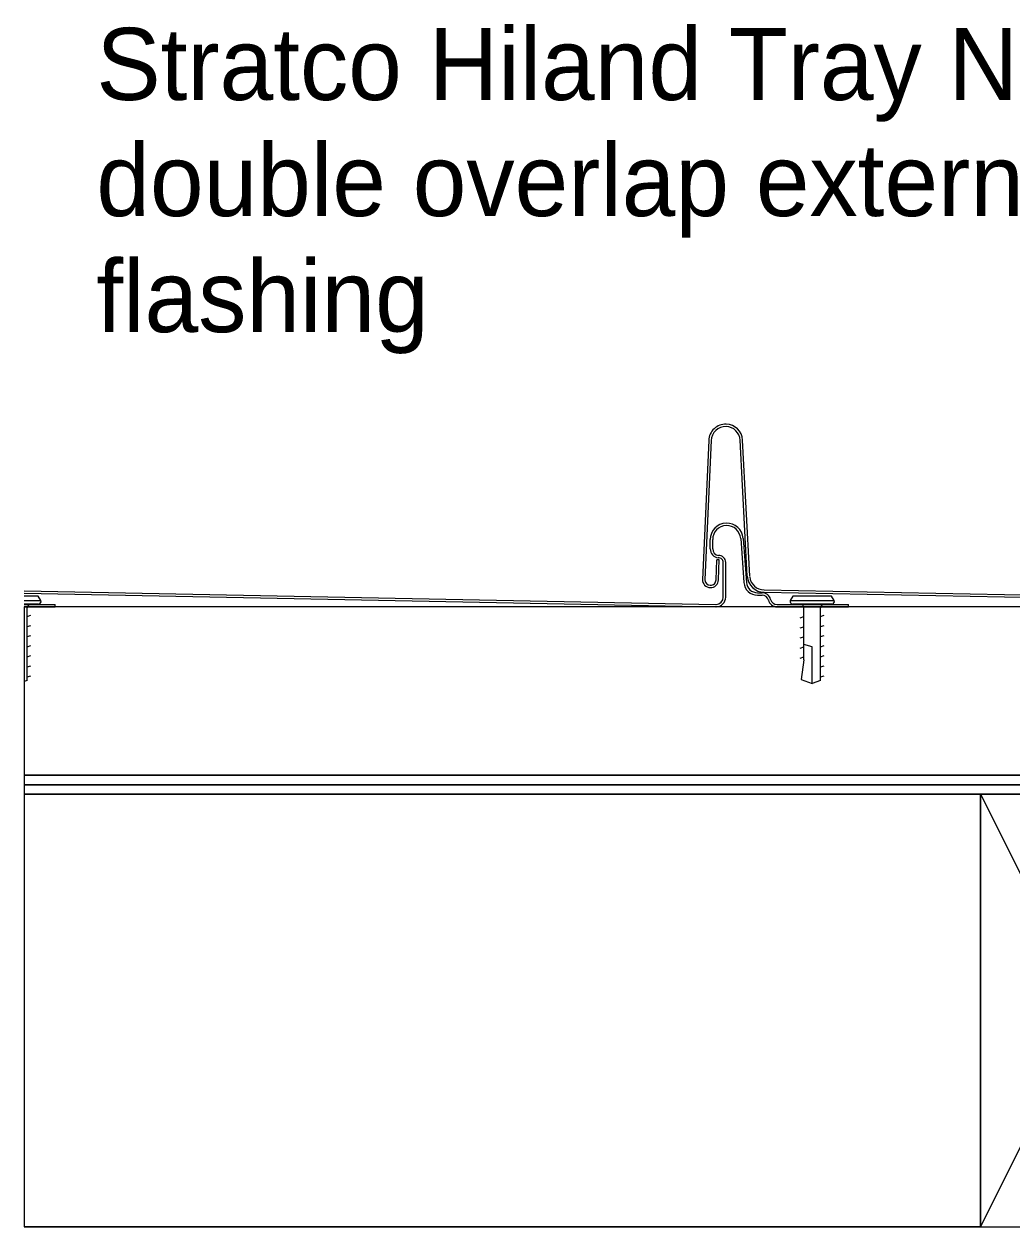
# Model space of a CAD drawing. Extents: x -2.36 to 6.66, y -3.72 to 4.13.
# Drawn here: x 1.2345 to 1.4399, y -3.129 to -2.8788 of the extents above; entities that cross this region are included whole.
import ezdxf

# ---------------------------------------------------------------- set-up
doc = ezdxf.new("R2010")
doc.units = 0
for name, color, linetype in [('A-____-____-IDEN', 7, 'Continuous'), ('A-DETL-____-MEDM', 7, 'Continuous'), ('A-DETL-GENF-OTLN', 7, 'Continuous'), ('A-WALL-____-MCUT', 7, 'Continuous'), ('A-WALL-____-PATT', 7, 'Continuous')]:
    doc.layers.add(name, color=color, linetype=linetype)

# ---------------------------------------------------------------- blocks, each defined once
blk = doc.blocks.new('Detail Repeating_Stratco_Hiland_Tray_Nailstrip - Rib Height 38mm_165mm Coverage-V13-Detail Flashings - Hiland Nailstrip Corner')
at = {"layer": 'A-DETL-____-MEDM'}
for p, q in [((0.32648096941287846, 0.03458502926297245), (0.32517240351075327, 0.005699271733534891)), ((0.32698063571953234, 0.034566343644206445), (0.32567207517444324, 0.005680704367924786)), ((0.3344987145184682, 0.0063452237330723), (0.33301561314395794, 0.0346381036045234)), ((0.3349980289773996, 0.00637139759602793), (0.3335149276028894, 0.03466427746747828)), ((0.3267942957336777, 0.012056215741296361), (0.3267942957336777, 0.013973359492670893)), ((0.3272942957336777, 0.012056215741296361), (0.3272942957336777, 0.013973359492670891)), ((0.33313551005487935, 0.014184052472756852), (0.3337958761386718, 0.005042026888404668)), ((0.3336342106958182, 0.014220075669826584), (0.3342945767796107, 0.005078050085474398)), ((0.49179429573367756, 0.01205621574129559), (0.49179429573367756, 0.013973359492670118)), ((0.49229429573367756, 0.01205621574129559), (0.49229429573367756, 0.013973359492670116)), ((0.4981355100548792, 0.014184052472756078), (0.4987958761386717, 0.005042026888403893)), ((0.49863421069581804, 0.014220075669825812), (0.4992945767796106, 0.005078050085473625)), ((0.3280061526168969, 0.005613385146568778), (0.3281320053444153, 0.009787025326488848)), ((0.32863177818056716, 0.009771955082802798), (0.3281320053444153, 0.009787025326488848)), ((0.3285059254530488, 0.005598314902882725), (0.32863177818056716, 0.009771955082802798)), ((0.32950000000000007, 0.0019999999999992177), (0.32950000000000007, 0.0092381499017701)), ((0.32999999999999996, 0.0019999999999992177), (0.32999999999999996, 0.0092381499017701)), ((0.49449999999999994, 0.0019999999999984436), (0.49449999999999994, 0.009238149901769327)), ((0.4949999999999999, 0.0019999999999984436), (0.4949999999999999, 0.009238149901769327)), ((0.18407252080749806, 0.0033120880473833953), (0.3279754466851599, 0.0005002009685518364)), ((0.18407252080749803, 0.002812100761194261), (0.3279672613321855, 2.679730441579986e-07)), ((0.33662103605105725, 0.0029135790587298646), (0.3375703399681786, 0.0029135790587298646)), ((0.3379999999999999, 0.003528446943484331), (0.4929754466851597, 0.0005002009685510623)), ((0.3380010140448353, 0.0030284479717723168), (0.4929672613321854, 2.679730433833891e-07)), ((0.5016210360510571, 0.00291357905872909), (0.5025703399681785, 0.00291357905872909)), ((0.184072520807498, 0.0004999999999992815), (0.1905651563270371, 0.0004999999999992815)), ((0.1905651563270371, -7.14861503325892e-16), (0.1905651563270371, 0.0004999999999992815)), ((0.33662103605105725, 0.002413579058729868), (0.3375703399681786, 0.002413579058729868)), ((0.3407106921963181, 0.0004999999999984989), (0.35556515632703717, 0.0004999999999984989)), ((0.35556515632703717, -1.4974022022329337e-15), (0.35556515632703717, 0.0004999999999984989)), ((0.5016210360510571, 0.0024135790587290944), (0.5025703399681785, 0.0024135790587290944)), ((0.5057106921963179, 0.0004999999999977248), (0.520565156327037, 0.0004999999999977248)), ((0.520565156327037, -2.2714830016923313e-15), (0.520565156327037, 0.0004999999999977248)), ((0.184072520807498, -7.14861503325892e-16), (0.1905651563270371, -7.14861503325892e-16)), ((0.3407106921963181, -1.4974022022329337e-15), (0.35556515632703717, -1.4974022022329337e-15)), ((0.5057106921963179, -2.2714830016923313e-15), (0.520565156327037, -2.2714830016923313e-15))]:
    blk.add_line(p, q, dxfattribs=at)
for centre, radius, start, end in [((0.3299996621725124, 0.03447919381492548), 0.0035202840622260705, 88.27177070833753, 178.27717358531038), ((0.33000033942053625, 0.03448004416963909), 0.0035194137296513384, 3.000675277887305, 88.2823737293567), ((0.3299996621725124, 0.03447919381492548), 0.0030202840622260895, 88.27089304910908, 178.3465096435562), ((0.33000033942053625, 0.03448004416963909), 0.0030194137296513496, 3.0006752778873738, 88.28325162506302), ((0.3302187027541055, 0.01397335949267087), 0.003424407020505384, 4.131533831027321, 179.99999999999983), ((0.3302187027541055, 0.01397335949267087), 0.002924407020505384, 4.131533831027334, 179.9999999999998), ((0.49521870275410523, 0.013973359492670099), 0.003424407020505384, 4.131533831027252, 179.99999999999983), ((0.49521870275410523, 0.013973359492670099), 0.002924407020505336, 4.131533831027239, 179.9999999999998), ((0.3286942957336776, 0.012056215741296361), 0.0019000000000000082, 180, 262.83254480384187), ((0.3286942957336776, 0.012056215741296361), 0.0013999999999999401, 180, 260.8454895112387), ((0.3285613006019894, 0.0092381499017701), 0.0009386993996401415, 0, 96.36507997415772), ((0.3285613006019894, 0.0092381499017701), 0.001438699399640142, 0, 93.57624011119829), ((0.4936942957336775, 0.01205621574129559), 0.0019000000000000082, 180, 262.83254480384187), ((0.4936942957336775, 0.01205621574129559), 0.0013999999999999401, 180, 260.8454895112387), ((0.4935613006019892, 0.009238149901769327), 0.0009386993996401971, 0, 96.36507997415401), ((0.4935613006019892, 0.009238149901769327), 0.0014386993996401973, 0, 93.57624011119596), ((0.3268385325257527, 0.005648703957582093), 0.0016668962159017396, 178.26158059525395, 268.3043897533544), ((0.3268385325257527, 0.005648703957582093), 0.0011668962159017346, 178.42855061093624, 268.31446649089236), ((0.3268398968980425, 0.005648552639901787), 0.001666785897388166, 268.25735606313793, 358.2728157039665), ((0.3268398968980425, 0.005648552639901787), 0.0011667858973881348, 268.2472785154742, 358.27281570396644), ((0.33662103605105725, 0.005246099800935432), 0.002832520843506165, 184.1315338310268, 269.99999999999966), ((0.33662103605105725, 0.005246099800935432), 0.002332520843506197, 184.13153383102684, 269.99999999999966), ((0.33799391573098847, 0.006528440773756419), 0.0034999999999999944, 183.00067527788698, 270.11620105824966), ((0.33799391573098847, 0.006528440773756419), 0.002999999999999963, 186.00067527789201, 270.116201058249), ((0.5016210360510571, 0.005246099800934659), 0.0028325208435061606, 184.1315338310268, 269.99999999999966), ((0.5016210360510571, 0.005246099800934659), 0.002332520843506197, 184.13153383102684, 269.99999999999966), ((0.3375703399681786, 0.0010676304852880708), 0.0018459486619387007, 14.910432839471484, 90.00000000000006), ((0.5025703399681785, 0.0010676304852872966), 0.0018459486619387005, 14.910432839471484, 90.00000000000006), ((0.32799999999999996, 0.0019999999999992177), 0.001999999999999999, 269.9999999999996, 5.684341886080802e-14), ((0.32799999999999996, 0.0019999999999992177), 0.0015000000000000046, 270.00000000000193, 359.9999999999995), ((0.3375703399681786, 0.0010676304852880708), 0.0013459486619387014, 14.9104328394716, 90.00000000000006), ((0.3407106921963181, 0.00190382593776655), 0.0019038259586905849, 194.91043283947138, 269.99999999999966), ((0.3407106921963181, 0.00190382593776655), 0.0014038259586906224, 194.91043283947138, 269.99999999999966), ((0.4929999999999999, 0.0019999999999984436), 0.001999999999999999, 269.9999999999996, 5.684341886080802e-14), ((0.4929999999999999, 0.0019999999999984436), 0.0015000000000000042, 270.0000000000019, 359.9999999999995), ((0.5025703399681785, 0.0010676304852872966), 0.001345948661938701, 14.910432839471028, 90.00000000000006), ((0.5057106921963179, 0.001903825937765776), 0.0019038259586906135, 194.91043283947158, 269.99999999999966), ((0.5057106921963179, 0.001903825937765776), 0.0014038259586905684, 194.9104328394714, 269.99999999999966)]:
    blk.add_arc(centre, radius, start, end, dxfattribs=at)
at = {"layer": 'A-DETL-GENF-OTLN'}
for p, q in [((0.1870052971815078, 0.0022175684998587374), (0.18407252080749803, 0.0022175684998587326)), ((0.18407252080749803, 0.0012874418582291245), (0.18755219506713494, 0.0012874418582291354)), ((0.1870999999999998, 0.0005769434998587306), (0.184072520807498, 0.0005769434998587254)), ((0.18755219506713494, 0.001287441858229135), (0.1870052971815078, 0.002217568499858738)), ((0.3439947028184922, 0.002217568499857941), (0.3434420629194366, 0.0012776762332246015)), ((0.3434478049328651, 0.0012874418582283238), (0.3525521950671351, 0.001287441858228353)), ((0.3520999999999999, 0.0005769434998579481), (0.34390000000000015, 0.0005769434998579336)), ((0.35200529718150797, 0.0022175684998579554), (0.34399470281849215, 0.002217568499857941)), ((0.3525521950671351, 0.0012874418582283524), (0.35200529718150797, 0.0022175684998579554)), ((0.508994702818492, 0.0022175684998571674), (0.5084420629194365, 0.0012776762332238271)), ((0.5084478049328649, 0.0012874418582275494), (0.5175521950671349, 0.001287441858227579)), ((0.5170999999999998, 0.000576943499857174), (0.5089, 0.0005769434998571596)), ((0.5170052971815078, 0.0022175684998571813), (0.508994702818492, 0.0022175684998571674)), ((0.5175521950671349, 0.0012874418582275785), (0.5170052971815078, 0.0022175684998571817)), ((0.18474999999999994, -0.015299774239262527), (0.1847499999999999, -0.000223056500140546)), ((0.1847499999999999, -0.00200932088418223), (0.1854999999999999, -0.0017713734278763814)), ((0.34550000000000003, -0.0022833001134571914), (0.34625, -0.0020453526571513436)), ((0.34625, -0.01102170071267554), (0.34625, -0.0002230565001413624)), ((0.34975000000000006, -0.015299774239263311), (0.34975, -0.00022305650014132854)), ((0.34975, -0.0020093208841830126), (0.3505, -0.001771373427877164)), ((0.5104999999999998, -0.002283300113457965), (0.5112499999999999, -0.0020453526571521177)), ((0.5112499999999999, -0.011021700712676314), (0.5112499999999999, -0.00022305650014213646)), ((0.5147499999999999, -0.015299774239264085), (0.5147499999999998, -0.00022305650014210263)), ((0.5147499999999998, -0.0020093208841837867), (0.5154999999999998, -0.001771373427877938)), ((0.18474999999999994, -0.004107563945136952), (0.18549999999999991, -0.0038696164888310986)), ((0.34550000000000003, -0.004381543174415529), (0.34625, -0.004143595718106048)), ((0.34975, -0.004107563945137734), (0.3505, -0.0038696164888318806)), ((0.5104999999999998, -0.004381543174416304), (0.5112499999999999, -0.004143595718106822)), ((0.5147499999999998, -0.004107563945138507), (0.5154999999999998, -0.003869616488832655)), ((0.18474999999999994, -0.006205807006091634), (0.18549999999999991, -0.005967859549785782)), ((0.34550000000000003, -0.006479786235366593), (0.34625, -0.0062418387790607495)), ((0.34975, -0.006205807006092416), (0.3505, -0.005967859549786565)), ((0.5104999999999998, -0.006479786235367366), (0.5112499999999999, -0.006241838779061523)), ((0.5147499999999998, -0.006205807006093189), (0.5154999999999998, -0.005967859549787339)), ((0.18474999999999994, -0.00830405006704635), (0.18549999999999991, -0.0080661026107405)), ((0.34550000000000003, -0.00857802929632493), (0.34625, -0.008340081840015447)), ((0.3479999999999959, -0.008320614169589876), (0.34625000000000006, -0.007818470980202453)), ((0.3479999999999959, -0.015936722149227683), (0.3479999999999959, -0.008320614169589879)), ((0.34975, -0.008304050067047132), (0.3505, -0.008066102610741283)), ((0.5104999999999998, -0.008578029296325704), (0.5112499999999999, -0.008340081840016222)), ((0.5129999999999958, -0.008320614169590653), (0.5112499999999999, -0.007818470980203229)), ((0.5129999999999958, -0.015936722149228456), (0.5129999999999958, -0.008320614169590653)), ((0.5147499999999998, -0.008304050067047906), (0.5154999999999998, -0.008066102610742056)), ((0.18474999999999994, -0.010402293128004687), (0.18549999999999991, -0.010164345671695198)), ((0.18474999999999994, -0.012500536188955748), (0.18549999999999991, -0.012262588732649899)), ((0.34550000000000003, -0.010676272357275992), (0.34625, -0.010438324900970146)), ((0.34625000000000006, -0.011021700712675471), (0.3456780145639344, -0.015091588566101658)), ((0.34975, -0.010402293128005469), (0.3505, -0.010164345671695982)), ((0.34975, -0.01250053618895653), (0.3505, -0.012262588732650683)), ((0.5104999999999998, -0.010676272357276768), (0.5112499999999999, -0.010438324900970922)), ((0.5112499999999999, -0.011021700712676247), (0.5106780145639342, -0.01509158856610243)), ((0.5147499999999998, -0.010402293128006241), (0.5154999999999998, -0.010164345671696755)), ((0.5147499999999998, -0.012500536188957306), (0.5154999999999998, -0.012262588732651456)), ((0.18474999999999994, -0.014598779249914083), (0.18549999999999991, -0.014360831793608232)), ((0.34975000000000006, -0.014598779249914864), (0.35050000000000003, -0.014360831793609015)), ((0.5147499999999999, -0.01459877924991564), (0.5154999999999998, -0.014360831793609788)), ((0.18474999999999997, -0.015299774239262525), (0.18407252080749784, -0.015546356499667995)), ((0.3456780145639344, -0.015091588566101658), (0.34800000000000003, -0.015936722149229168)), ((0.34975000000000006, -0.015299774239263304), (0.34800000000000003, -0.015936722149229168)), ((0.5106780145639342, -0.01509158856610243), (0.5129999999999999, -0.01593672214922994)), ((0.5147499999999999, -0.015299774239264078), (0.5129999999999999, -0.01593672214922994))]:
    blk.add_line(p, q, dxfattribs=at)
for centre, radius, start, end in [((0.18554999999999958, -0.000223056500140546), 0.0008, 90.00000000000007, 180.00000000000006), ((0.18709999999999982, 0.0010769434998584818), 0.0005000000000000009, 269.9999999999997, 23.66982389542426), ((0.34390000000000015, 0.0010769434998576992), 0.0005000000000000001, 156.3301761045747, 269.99999999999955), ((0.34545000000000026, -0.0002230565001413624), 0.000800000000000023, 1.2722218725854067e-14, 90.00000000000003), ((0.35054999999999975, -0.00022305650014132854), 0.000800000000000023, 90.00000000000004, 180.00000000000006), ((0.3520999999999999, 0.0010769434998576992), 0.0005000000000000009, 269.9999999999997, 23.669823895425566), ((0.5089, 0.0010769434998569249), 0.0005, 156.33017610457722, 269.99999999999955), ((0.5104500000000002, -0.00022305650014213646), 0.0008000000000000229, 359.99999999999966, 90.00000000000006), ((0.5155499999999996, -0.00022305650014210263), 0.000800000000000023, 90.00000000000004, 180.00000000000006), ((0.5170999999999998, 0.0010769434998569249), 0.000500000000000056, 269.9999999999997, 23.66982389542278)]:
    blk.add_arc(centre, radius, start, end, dxfattribs=at)
blk = doc.blocks.new('DET_ST_Framing Detail Timber - 45x90-V12-Detail Flashings - Hiland Nailstrip Corner')
at = {"layer": 'A-DETL-____-MEDM'}
for p, q in [((0.09000000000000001, 0.045000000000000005), (0, 0.045000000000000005)), ((0, 0.045000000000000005), (0, 0)), ((0.09000000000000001, 0), (0.09000000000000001, 0.045000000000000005)), ((0, 0), (0.09000000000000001, 0))]:
    blk.add_line(p, q, dxfattribs=at)
at = {"layer": 'A-DETL-GENF-OTLN'}
for p, q in [((0, 0.04500000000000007), (0.09000000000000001, 0)), ((0.09000000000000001, 0.045000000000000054), (0, 0))]:
    blk.add_line(p, q, dxfattribs=at)

msp = doc.modelspace()

# ---------------------------------------------------------------- linework, layer by layer
at = {"layer": 'A-WALL-____-MCUT'}
for p, q in [((1.5373138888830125, -3.0000000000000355), (1.2344801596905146, -3.0000000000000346)), ((1.5373138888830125, -3.035000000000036), (1.2344801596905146, -3.0350000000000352)), ((1.570407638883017, -3.0370000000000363), (1.2344801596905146, -3.037000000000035)), ((1.4334076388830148, -3.0390000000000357), (1.2344801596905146, -3.039000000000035)), ((1.433407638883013, -3.129000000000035), (1.2344801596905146, -3.129000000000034))]:
    msp.add_line(p, q, dxfattribs=at)
at = {"layer": 'A-WALL-____-PATT'}
for p, q in [((1.5373138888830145, -3.000000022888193), (1.2344801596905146, -3.000000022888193)), ((1.2344801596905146, -3.000000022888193), (1.2344801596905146, -3.0349999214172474)), ((1.2344801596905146, -3.0349999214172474), (1.5373138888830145, -3.0349999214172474)), ((1.5724076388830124, -3.035000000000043), (1.2344801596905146, -3.035000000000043)), ((1.2344801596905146, -3.035000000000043), (1.2344801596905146, -3.037000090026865)), ((1.2344801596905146, -3.037000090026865), (1.556755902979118, -3.037000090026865)), ((1.5704070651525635, -3.037000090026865), (1.2344801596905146, -3.037000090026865)), ((1.2344801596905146, -3.037000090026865), (1.2344801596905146, -3.0389999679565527)), ((1.2344801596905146, -3.0389999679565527), (1.5684071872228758, -3.0389999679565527)), ((1.4334076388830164, -3.0390000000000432), (1.2344801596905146, -3.0390000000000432)), ((1.2344801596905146, -3.0390000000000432), (1.2344801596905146, -3.1289999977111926)), ((1.4334076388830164, -3.1289999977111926), (1.4334076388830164, -3.0390000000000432)), ((1.2344801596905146, -3.1289999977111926), (1.4334076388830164, -3.1289999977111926))]:
    msp.add_line(p, q, dxfattribs=at)

# ---------------------------------------------------------------- block references
at = {"layer": 'A-DETL-GENF-OTLN'}
msp.add_blockref('Detail Repeating_Stratco_Hiland_Tray_Nailstrip - Rib Height 38mm_165mm Coverage-V13-Detail Flashings - Hiland Nailstrip Corner', (1.0504076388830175, -3.000000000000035), dxfattribs=at)
at = {"layer": 'A-DETL-GENF-OTLN', "rotation": 89.9999999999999}
msp.add_blockref('DET_ST_Framing Detail Timber - 45x90-V12-Detail Flashings - Hiland Nailstrip Corner', (1.4784076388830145, -3.1290000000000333), dxfattribs=at)

# ---------------------------------------------------------------- texts
at = {"layer": 'A-____-____-IDEN'}
for s, p in [('Stratco Hiland Tray Nailstrip', (1.2495100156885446, -2.8945770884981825)), ('double overlap external corner', (1.2495100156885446, -2.918720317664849)), ('flashing', (1.2495100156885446, -2.942863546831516))]:
    msp.add_text(s, height=0.014999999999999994, dxfattribs=at).set_placement(p)

doc.saveas('drawing.dxf')
